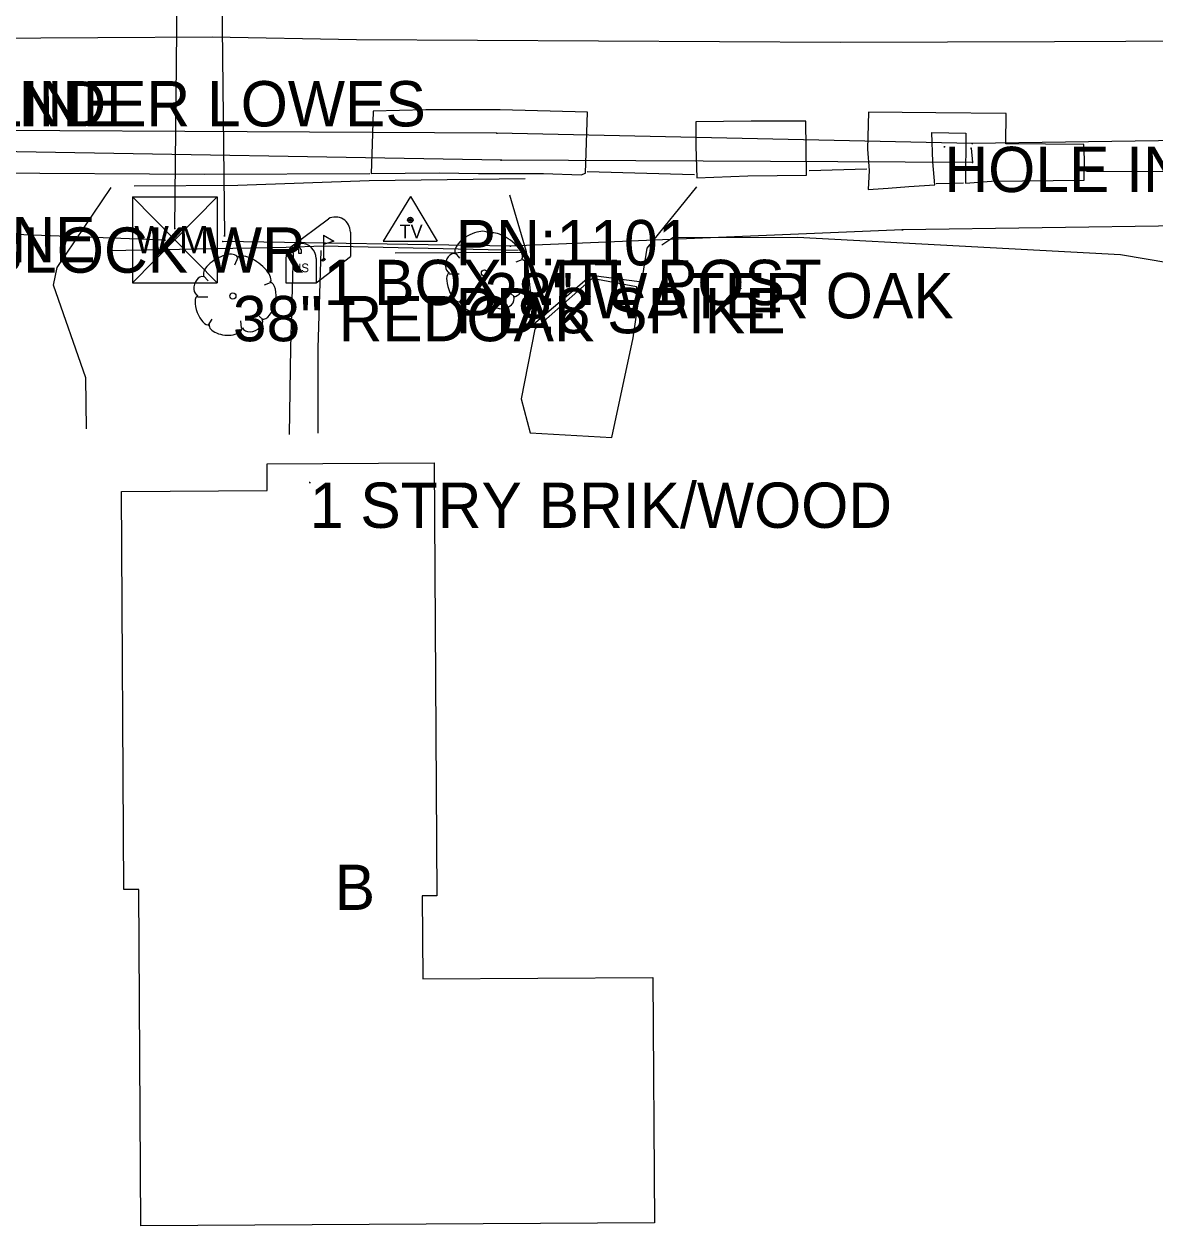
# Model space of a CAD drawing. Extents: x 1304270 to 1306561, y 1876019 to 1876752.
# Drawn here: x 1305299.9 to 1305424.7, y 1876276 to 1876408.6 of the extents above; entities that cross this region are included whole.
import ezdxf

# ---------------------------------------------------------------- set-up
doc = ezdxf.new("R2010")
doc.units = 0
for name, color, linetype in [('S_BUILDING', 7, 'Continuous'), ('S_BUILDING_ANNOT', 7, 'Continuous'), ('S_DRIVEWAY', 7, 'Continuous'), ('S_EDGE_CONCRETE', 7, 'Continuous'), ('S_EDGE_PAVEMENT', 7, 'Continuous'), ('S_ELECTRIC_UTILITIES_ANNOT', 7, 'Continuous'), ('S_FIBER_OPTIC_CABLE', 7, 'Continuous'), ('S_GAS_UTILITIES', 7, 'Continuous'), ('S_MAILBOX', 7, 'Continuous'), ('S_MAILBOX_ANNOT', 7, 'Continuous'), ('S_MISC_STRUCTURES_ANNOT', 7, 'Continuous'), ('S_MSC_PT_SYM', 7, 'Continuous'), ('S_PAVEMENT_CROWN', 7, 'Continuous'), ('S_SECONDARY_CTL', 7, 'Continuous'), ('S_SECONDARY_CTL_ANNOT', 7, 'Continuous'), ('S_SHOULDER', 7, 'Continuous'), ('S_SIDEWALK', 7, 'Continuous'), ('S_SIGN_ANNOT', 7, 'Continuous'), ('S_STR_PT_SYM', 7, 'Continuous'), ('S_SURVEY_TEXT_ANNOT', 7, 'Continuous'), ('S_TREE', 7, 'Continuous'), ('S_TREE_ANNOT', 7, 'Continuous'), ('S_UTL_PT_SYM', 7, 'Continuous'), ('S_WATER_UTILITIES', 7, 'Continuous')]:
    doc.layers.add(name, color=color, linetype=linetype)

msp = doc.modelspace()

# ---------------------------------------------------------------- linework, layer by layer
at = {"layer": 'S_BUILDING'}
msp.add_lwpolyline([(1305310.93, 1876313.13), (1305310.66, 1876357.05), (1305326.75, 1876357.15), (1305326.73, 1876360.08), (1305345.18, 1876360.2), (1305345.48, 1876312.43), (1305343.85, 1876312.42), (1305343.91, 1876303.27), (1305369.32, 1876303.43), (1305369.48, 1876276.35), (1305312.8, 1876276), (1305312.57, 1876313.14)], close=True, dxfattribs=at)
at = {"layer": 'S_DRIVEWAY'}
for points in [[(1305306.79, 1876363.96), (1305306.72, 1876369.58), (1305303.16, 1876379.8), (1305303.55, 1876381.77), (1305309.51, 1876390.59)], [(1305353.48, 1876389.76), (1305355.34, 1876383.51), (1305356.14, 1876375.49), (1305362.49, 1876380.92), (1305368.08, 1876380.18), (1305368.67, 1876383.89), (1305374.15, 1876390.65)], [(1305367.52, 1876379.64), (1305362.6, 1876380.56), (1305356.28, 1876374.96), (1305354.76, 1876367.26), (1305355.77, 1876363.52), (1305364.77, 1876363), (1305367.13, 1876374), (1305367.78, 1876378.53)], [(1305367.78, 1876378.53), (1305367.52, 1876379.64)]]:
    msp.add_lwpolyline(points, dxfattribs=at)
at = {"layer": 'S_EDGE_CONCRETE'}
for points in [[(1305338.23, 1876392.12), (1305345.73, 1876392.22), (1305350.07, 1876392.12), (1305357.23, 1876392.12), (1305361.39, 1876392), (1305361.88, 1876392.18), (1305362.09, 1876398.89), (1305352.44, 1876399.15), (1305344.24, 1876399.17), (1305338.44, 1876399.02), (1305338.33, 1876395.36)], [(1305374.16, 1876391.66), (1305379.78, 1876391.86), (1305386.28, 1876391.96), (1305386.22, 1876394.93), (1305386.19, 1876397.89), (1305380.17, 1876397.91), (1305374.07, 1876397.85), (1305374.05, 1876395.15)], [(1305393.11, 1876398.9), (1305393.01, 1876394.81), (1305393.2, 1876392.48), (1305393.09, 1876390.37), (1305395.28, 1876390.51), (1305397.55, 1876390.69), (1305400.42, 1876390.89), (1305400.23, 1876393.41), (1305400.09, 1876396.67), (1305403.86, 1876396.58), (1305403.82, 1876391.07), (1305406.7, 1876391.27), (1305416.9, 1876391.4), (1305416.95, 1876393.69), (1305416.88, 1876395.33), (1305412.65, 1876395.38), (1305408.26, 1876395.42), (1305408.32, 1876398.75), (1305400.54, 1876398.83)]]:
    msp.add_lwpolyline(points, close=True, dxfattribs=at)
at = {"layer": 'S_EDGE_PAVEMENT'}
for points in [[(1305254, 1876392.45), (1305271.4, 1876392.34), (1305295.59, 1876392.2), (1305319.77, 1876392.05), (1305338.06, 1876392.13)], [(1305362.04, 1876392.34), (1305373.89, 1876392.01)], [(1305386.55, 1876392.48), (1305392.93, 1876392.64)], [(1305417.16, 1876392.4), (1305436.21, 1876392.32)], [(1305400.57, 1876391.02), (1305403.61, 1876391.1)]]:
    msp.add_lwpolyline(points, dxfattribs=at)
at = {"layer": 'S_FIBER_OPTIC_CABLE'}
for p, q in [((1305352.56, 1876393.61), (1305019.82, 1876399.32)), ((1305352.1, 1876396.58), (1305247.6, 1876397.15)), ((1305404.56, 1876395.44), (1305352.1, 1876396.58)), ((1305449.61, 1876396.12), (1305404.56, 1876395.44)), ((1305404.59, 1876393.35), (1305352.56, 1876393.61)), ((1305404.44, 1876394.92), (1305404.59, 1876393.35))]:
    msp.add_line(p, q, dxfattribs=at)
at = {"layer": 'S_GAS_UTILITIES'}
for p, q in [((1305321.24, 1876463.46), (1305322.01, 1876385.24)), ((1305315.46, 1876384.79), (1305245.22, 1876387.43)), ((1305396.85, 1876385.91), (1305353.59, 1876384.13)), ((1305434.19, 1876386.43), (1305396.85, 1876385.91)), ((1305353.59, 1876384.13), (1305321.84, 1876384.63))]:
    msp.add_line(p, q, dxfattribs=at)
at = {"layer": 'S_MAILBOX'}
for p, q in [((1305329.36, 1876384.04), (1305333.49, 1876387.14)), ((1305335.92, 1876385.67), (1305335.92, 1876382.96)), ((1305332.97, 1876385.32), (1305332.97, 1876382.61)), ((1305328.8, 1876382.76), (1305328.8, 1876380.05)), ((1305332.13, 1876380.05), (1305335.92, 1876382.96)), ((1305332.13, 1876382.76), (1305332.13, 1876380.05)), ((1305328.8, 1876380.05), (1305332.13, 1876380.05))]:
    msp.add_line(p, q, dxfattribs=at)
for points in [[(1305332.97, 1876385.32), (1305334.08, 1876384.66), (1305332.97, 1876384.31)], [(1305329.99, 1876383.88), (1305330.21, 1876383.74), (1305330.21, 1876383.35), (1305330.51, 1876383.35), (1305330.51, 1876383.71), (1305330.32, 1876383.96), (1305329.99, 1876383.9)]]:
    msp.add_lwpolyline(points, dxfattribs=at)
for centre, end in [((1305334.26, 1876385.67), 117.5718), ((1305330.47, 1876382.76), 180)]:
    msp.add_arc(centre, 1.66, 0, end, dxfattribs=at)
msp.add_ellipse((1305332.97, 1876382.61), major_axis=(0.145, 0.132), ratio=0.564646, dxfattribs=at)
at = {"layer": 'S_MSC_PT_SYM'}
msp.add_lwpolyline([(1305401.49, 1876395.08), (1305401.49, 1876395.13), (1305401.49, 1876395.08), (1305401.44, 1876395.08), (1305401.49, 1876395.08), (1305401.49, 1876395.03), (1305401.49, 1876395.08), (1305401.54, 1876395.08)], dxfattribs=at)
at = {"layer": 'S_PAVEMENT_CROWN'}
msp.add_lwpolyline([(1305132.34, 1876408.05), (1305154.42, 1876408.07), (1305176.49, 1876408.08), (1305199.49, 1876407.69), (1305222.49, 1876407.31), (1305246.33, 1876407.09), (1305270.17, 1876406.88), (1305282.8, 1876406.96), (1305295.42, 1876407.05), (1305308.05, 1876407.14), (1305320.68, 1876407.22), (1305336.61, 1876406.9), (1305349.96, 1876406.83), (1305363.32, 1876406.76), (1305376.67, 1876406.68), (1305390.03, 1876406.61), (1305413.65, 1876406.71), (1305437.28, 1876406.8)], dxfattribs=at)
at = {"layer": 'S_SECONDARY_CTL'}
for p, q in [((1305342.54, 1876389.61), (1305339.53, 1876384.66)), ((1305342.54, 1876389.61), (1305345.49, 1876384.66)), ((1305339.53, 1876384.66), (1305345.49, 1876384.66))]:
    msp.add_line(p, q, dxfattribs=at)
for radius in [0.311, 0.183, 0.103]:
    msp.add_circle((1305342.54, 1876387), radius, dxfattribs=at)
at = {"layer": 'S_SHOULDER'}
for points in [[(1305355.2, 1876391.55), (1305338, 1876391.34), (1305323.49, 1876390.79), (1305312.04, 1876390.72)], [(1305370.31, 1876384.27), (1305371.53, 1876385.07), (1305385.28, 1876385.09), (1305403.11, 1876384.15), (1305420.94, 1876383.2), (1305437.03, 1876380.49)], [(1305309.17, 1876383.65), (1305328.84, 1876384), (1305332.93, 1876384.14), (1305354.46, 1876383.69)], [(1305340.85, 1876383.38), (1305354.79, 1876383.45)]]:
    msp.add_lwpolyline(points, dxfattribs=at)
at = {"layer": 'S_SIDEWALK'}
for points in [[(1305329.6, 1876383.38), (1305329.31, 1876372.93), (1305329.17, 1876363.33)], [(1305332.35, 1876363.47), (1305332.37, 1876372.86), (1305332.7, 1876383.64)]]:
    msp.add_lwpolyline(points, dxfattribs=at)
at = {"layer": 'S_STR_PT_SYM'}
msp.add_lwpolyline([(1305331.44, 1876358.03), (1305331.44, 1876358.08), (1305331.44, 1876358.03), (1305331.39, 1876358.03), (1305331.44, 1876358.03), (1305331.44, 1876357.98), (1305331.44, 1876358.03), (1305331.49, 1876358.03)], dxfattribs=at)
at = {"layer": 'S_TREE'}
for p, q in [((1305351.28, 1876385.4), (1305350.89, 1876384.55)), ((1305347.48, 1876383.39), (1305347.98, 1876382.8)), ((1305323.51, 1876382.87), (1305323.12, 1876382.02)), ((1305354.84, 1876382.61), (1305354.18, 1876382.34)), ((1305319.71, 1876380.85), (1305320.22, 1876380.27)), ((1305346.82, 1876381.06), (1305347.94, 1876381.06)), ((1305327.08, 1876380.08), (1305326.42, 1876379.81)), ((1305319.06, 1876378.53), (1305320.18, 1876378.53)), ((1305347.98, 1876377.88), (1305348.45, 1876378.58)), ((1305351.66, 1876377.61), (1305351.59, 1876378.39)), ((1305354.07, 1876378.5), (1305353.6, 1876378.93)), ((1305326.3, 1876375.97), (1305325.84, 1876376.4)), ((1305320.22, 1876375.35), (1305320.68, 1876376.05)), ((1305323.9, 1876375.08), (1305323.82, 1876375.86))]:
    msp.add_line(p, q, dxfattribs=at)
for centre in [(1305350.72, 1876381.15), (1305322.95, 1876378.62)]:
    msp.add_circle(centre, 0.341, dxfattribs=at)
for centre, major_axis, ratio, start_param, end_param in [((1305349.38, 1876384.36), (1.86, 1.08), 0.471018, 0, 3.141593), ((1305353.04, 1876384.03), (-1.81, 1.36), 0.405113, 3.141593, 6.283186), ((1305321.62, 1876381.83), (1.86, 1.08), 0.471018, 0, 3.141593), ((1305325.27, 1876381.5), (-1.81, 1.36), 0.405113, 3.141593, 6.283186), ((1305347.15, 1876382.24), (0.31, 1.03), 0.646762, 0, 3.141593), ((1305354.39, 1876380.62), (0.46, 2.04), 0.482994, 3.141593, 6.283185), ((1305319.38, 1876379.71), (0.31, 1.03), 0.646762, 0, 3.141593), ((1305347.45, 1876379.59), (-0.61, 1.6), 0.420543, 6.283185, 9.424777), ((1305326.63, 1876378.09), (0.46, 2.04), 0.482994, 3.141593, 6.283185), ((1305319.69, 1876377.06), (-0.61, 1.6), 0.420543, 6.283185, 9.424777), ((1305349.91, 1876377.81), (-1.83, 0.19), 0.529943, 0, 3.141593), ((1305352.87, 1876378.1), (1.09, 0.46), 0.711534, 3.141592, 6.283185), ((1305322.15, 1876375.28), (-1.83, 0.19), 0.529943, 0, 3.141593), ((1305325.11, 1876375.57), (1.09, 0.46), 0.711534, 3.141592, 6.283185)]:
    msp.add_ellipse(centre, major_axis=major_axis, ratio=ratio, start_param=start_param, end_param=end_param, dxfattribs=at)
at = {"layer": 'S_UTL_PT_SYM'}
for points in [[(1305352.1, 1876396.58), (1305352.1, 1876396.63), (1305352.1, 1876396.58), (1305352.05, 1876396.58), (1305352.1, 1876396.58), (1305352.1, 1876396.53), (1305352.1, 1876396.58), (1305352.15, 1876396.58)], [(1305404.44, 1876394.92), (1305404.44, 1876394.97), (1305404.44, 1876394.92), (1305404.39, 1876394.92), (1305404.44, 1876394.92), (1305404.44, 1876394.87), (1305404.44, 1876394.92), (1305404.49, 1876394.92)], [(1305404.56, 1876395.44), (1305404.56, 1876395.49), (1305404.56, 1876395.44), (1305404.51, 1876395.44), (1305404.56, 1876395.44), (1305404.56, 1876395.39), (1305404.56, 1876395.44), (1305404.61, 1876395.44)], [(1305352.56, 1876393.61), (1305352.56, 1876393.66), (1305352.56, 1876393.61), (1305352.51, 1876393.61), (1305352.56, 1876393.61), (1305352.56, 1876393.56), (1305352.56, 1876393.61), (1305352.61, 1876393.61)], [(1305404.59, 1876393.35), (1305404.59, 1876393.4), (1305404.59, 1876393.35), (1305404.54, 1876393.35), (1305404.59, 1876393.35), (1305404.59, 1876393.3), (1305404.59, 1876393.35), (1305404.64, 1876393.35)], [(1305316.53, 1876386.06), (1305316.53, 1876386.11), (1305316.53, 1876386.06), (1305316.48, 1876386.06), (1305316.53, 1876386.06), (1305316.53, 1876386.01), (1305316.53, 1876386.06), (1305316.58, 1876386.06)], [(1305396.85, 1876385.91), (1305396.85, 1876385.96), (1305396.85, 1876385.91), (1305396.8, 1876385.91), (1305396.85, 1876385.91), (1305396.85, 1876385.86), (1305396.85, 1876385.91), (1305396.9, 1876385.91)], [(1305315.46, 1876384.79), (1305315.46, 1876384.84), (1305315.46, 1876384.79), (1305315.41, 1876384.79), (1305315.46, 1876384.79), (1305315.46, 1876384.74), (1305315.46, 1876384.79), (1305315.51, 1876384.79)], [(1305321.84, 1876384.63), (1305321.84, 1876384.68), (1305321.84, 1876384.63), (1305321.79, 1876384.63), (1305321.84, 1876384.63), (1305321.84, 1876384.58), (1305321.84, 1876384.63), (1305321.89, 1876384.63)], [(1305322.01, 1876385.24), (1305322.01, 1876385.29), (1305322.01, 1876385.24), (1305321.96, 1876385.24), (1305322.01, 1876385.24), (1305322.01, 1876385.19), (1305322.01, 1876385.24), (1305322.06, 1876385.24)], [(1305353.59, 1876384.13), (1305353.59, 1876384.18), (1305353.59, 1876384.13), (1305353.54, 1876384.13), (1305353.59, 1876384.13), (1305353.59, 1876384.08), (1305353.59, 1876384.13), (1305353.64, 1876384.13)]]:
    msp.add_lwpolyline(points, dxfattribs=at)
at = {"layer": 'S_WATER_UTILITIES'}
for p, q in [((1305316.53, 1876386.06), (1305316.89, 1876419.56)), ((1305311.89, 1876389.57), (1305321.23, 1876389.57)), ((1305311.89, 1876389.57), (1305311.89, 1876380.07)), ((1305311.89, 1876389.57), (1305321.23, 1876380.07)), ((1305321.23, 1876389.57), (1305311.89, 1876380.07)), ((1305321.23, 1876389.57), (1305321.23, 1876380.07)), ((1305311.89, 1876380.07), (1305321.23, 1876380.07))]:
    msp.add_line(p, q, dxfattribs=at)

# ---------------------------------------------------------------- texts
at = {"layer": 'S_BUILDING_ANNOT'}
for s, p in [('1 STRY BRIK/WOOD', (1305331.44, 1876353.03)), ('B', (1305334.19, 1876310.87))]:
    msp.add_text(s, height=5, dxfattribs=at).set_placement(p)
at = {"layer": 'S_ELECTRIC_UTILITIES_ANNOT'}
msp.add_text('POINT ON ROAD UNDER LOWES', height=5, dxfattribs=at).set_placement((1305239.12, 1876397.33))
at = {"layer": 'S_MAILBOX'}
msp.add_text('US', height=0.96, rotation=360, dxfattribs=at).set_placement((1305329.57, 1876381.24))
at = {"layer": 'S_MAILBOX_ANNOT'}
msp.add_text('1 BOX MTL POST', height=5, dxfattribs=at).set_placement((1305332.97, 1876377.61))
at = {"layer": 'S_MISC_STRUCTURES_ANNOT'}
msp.add_text('CENDER BLOCK WR', height=5, dxfattribs=at).set_placement((1305265.25, 1876381.18))
at = {"layer": 'S_SECONDARY_CTL'}
msp.add_text('TV', height=1.5, rotation=360, dxfattribs=at).set_placement((1305341.34, 1876384.99))
at = {"layer": 'S_SECONDARY_CTL_ANNOT'}
for s, p in [('PN:1101', (1305347.54, 1876382)), ('PD:8 SPIKE', (1305347.54, 1876374.5))]:
    msp.add_text(s, height=5, dxfattribs=at).set_placement(p)
at = {"layer": 'S_SIGN_ANNOT'}
msp.add_text('0 MTL/WITH ELECTRIC NONE NONE', height=5, dxfattribs=at).set_placement((1305192.64, 1876382.34))
at = {"layer": 'S_SURVEY_TEXT_ANNOT'}
for s, p in [('LOWEST UTILITY LINE', (1305239.12, 1876397.33)), ('HOLE IN ROAD BED/ FILLED WITH P', (1305401.49, 1876390.08))]:
    msp.add_text(s, height=5, dxfattribs=at).set_placement(p)
at = {"layer": 'S_TREE_ANNOT'}
for s, p in [('28" WATER OAK', (1305350.72, 1876376.15)), ('38" REDOAK', (1305322.95, 1876373.62))]:
    msp.add_text(s, height=5, dxfattribs=at).set_placement(p)
at = {"layer": 'S_WATER_UTILITIES'}
msp.add_text('W M', height=3, rotation=360, dxfattribs=at).set_placement((1305312.09, 1876383.33))

doc.saveas('drawing.dxf')
